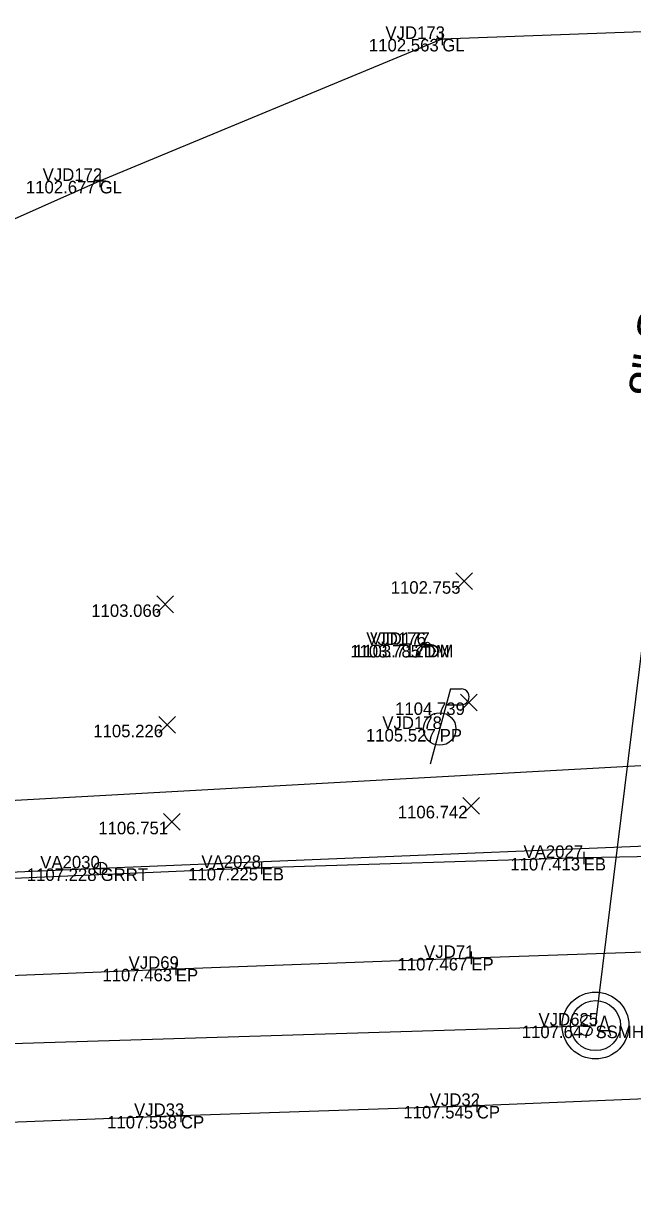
# Model space of a CAD drawing. Extents: x 1629915 to 1630675, y 484401 to 484601.
# Drawn here: x 1630207 to 1630255.7, y 484481.8 to 484574.6 of the extents above; entities that cross this region are included whole.
import ezdxf

# ---------------------------------------------------------------- set-up
doc = ezdxf.new("R2010")
doc.units = 0
for name, color, linetype in [('Default', 7, 'Continuous'), ('DR_X_Storm_Sewer', 7, 'Continuous'), ('GK_Drainage_Nodes', 7, 'Continuous'), ('PV_X_COP', 7, 'Continuous'), ('PV_X_EOP', 7, 'Continuous'), ('PV_X_Shoulder_Aggregate', 7, 'Continuous'), ('RD_X_GR_Rt', 7, 'Continuous'), ('SC_Scratch2', 7, 'Continuous'), ('SV_X_Random_Point', 7, 'Continuous'), ('SV_X_Shot_Marker', 7, 'Continuous'), ('SV_X_Text_Comment', 7, 'Continuous'), ('SV_X_Text_Elevation', 7, 'Continuous'), ('SV_X_Text_Name', 7, 'Continuous'), ('TX_X_20', 7, 'Continuous'), ('UT_X_Electric_Cells', 7, 'Continuous'), ('UT_X_Gas', 7, 'Continuous'), ('UT_X_Misc_Cells', 7, 'Continuous'), ('UT_X_Sanitary_Cells', 7, 'Continuous'), ('UT_X_Sanitary_Line', 7, 'Continuous')]:
    doc.layers.add(name, color=color, linetype=linetype)

# ---------------------------------------------------------------- blocks, each defined once
blk = doc.blocks.new('SurveyPointCell')
at = {"layer": 'Default'}
for p, q in [((-0.5, 0), (0.5, 0)), ((0, -0.5), (0, 0.5))]:
    blk.add_line(p, q, dxfattribs=at)
blk.add_circle((0, 0), 0.5, dxfattribs=at)

msp = doc.modelspace()

# ---------------------------------------------------------------- linework, layer by layer
at = {"layer": 'DR_X_Storm_Sewer'}
msp.add_line((1630034.139, 484503.088), (1630277.798, 484516.548), dxfattribs=at)
at = {"layer": 'GK_Drainage_Nodes'}
for p, q in [((1630252.717, 484496.605), (1630252.717, 484496.605)), ((1630252.717, 484494.605), (1630252.717, 484494.605)), ((1630252.717, 484494.605), (1630252.717, 484494.605)), ((1630252.717, 484494.605), (1630252.717, 484494.605)), ((1630252.717, 484492.605), (1630252.717, 484492.605))]:
    msp.add_line(p, q, dxfattribs=at)
msp.add_circle((1630252.717, 484494.605), 2, dxfattribs=at)
at = {"layer": 'PV_X_COP'}
msp.add_lwpolyline([(1630268.327, 484489.246), (1630243.236, 484488.193), (1630219.614, 484487.396), (1630181.886, 484485.929), (1630141.907, 484484.591), (1630101.847, 484483.155), (1630058.972, 484481.674), (1630018.452, 484480.335), (1629978.036, 484478.791), (1629939.203, 484477.211)], dxfattribs=at)
at = {"layer": 'PV_X_EOP'}
msp.add_lwpolyline([(1629938.787, 484488.624), (1629977.755, 484490.201), (1630018.109, 484491.66), (1630058.596, 484492.972), (1630101.458, 484494.639), (1630141.527, 484496.094), (1630181.4, 484497.615), (1630219.199, 484499.135), (1630242.799, 484500.003), (1630272.749, 484501.051)], dxfattribs=at)
at = {"layer": 'PV_X_Shoulder_Aggregate'}
msp.add_lwpolyline([(1630275.858, 484507.82), (1630275.935, 484508.43), (1630251.773, 484507.981), (1630226.056, 484507.184), (1630204.993, 484506.289), (1630180.178, 484504.732), (1630155.752, 484502.786), (1630130.505, 484501.377), (1630107.341, 484499.869), (1630082.614, 484498.877), (1630057.423, 484497.854), (1630056.684, 484498.178), (1630055.974, 484498.791), (1630036.737, 484497.117), (1630036.516, 484496.78), (1630005.439, 484492.996), (1629981.146, 484491.329), (1629968.094, 484490.842), (1629967.166, 484490.748), (1629965.306, 484491.801), (1629947.85, 484491.524), (1629935.773, 484490.2), (1629921.037, 484489.433)], dxfattribs=at)
at = {"layer": 'RD_X_GR_Rt'}
msp.add_lwpolyline([(1630276.942, 484509.755), (1630213.199, 484507.144), (1630188.359, 484506.044), (1630165.142, 484504.69)], dxfattribs=at)
at = {"layer": 'SV_X_Random_Point'}
for p, q in [((1630241.562, 484529.396), (1630242.896, 484530.731)), ((1630241.562, 484530.731), (1630242.896, 484529.396)), ((1630217.683, 484527.547), (1630219.017, 484528.882)), ((1630217.683, 484528.882), (1630219.017, 484527.547)), ((1630241.925, 484519.721), (1630243.258, 484521.056)), ((1630241.925, 484521.056), (1630243.258, 484519.721)), ((1630217.844, 484517.943), (1630219.178, 484519.278)), ((1630217.844, 484519.278), (1630219.178, 484517.943)), ((1630242.129, 484511.472), (1630243.462, 484512.807)), ((1630242.129, 484512.807), (1630243.462, 484511.472)), ((1630218.225, 484510.198), (1630219.559, 484511.533)), ((1630218.225, 484511.533), (1630219.559, 484510.198))]:
    msp.add_line(p, q, dxfattribs=at)
at = {"layer": 'SV_X_Shot_Marker'}
for p, q in [((1630239.982, 484573.334), (1630240.982, 484573.334)), ((1630240.482, 484573.834), (1630240.482, 484572.834)), ((1630240.482, 484573.334), (1630240.482, 484573.334)), ((1630213.122, 484562.506), (1630213.122, 484561.506)), ((1630212.622, 484562.006), (1630213.622, 484562.006)), ((1630213.122, 484562.006), (1630213.122, 484562.006)), ((1630251.773, 484508.481), (1630251.773, 484507.481)), ((1630226.056, 484507.684), (1630226.056, 484506.684)), ((1630251.273, 484507.981), (1630252.273, 484507.981)), ((1630251.773, 484507.981), (1630251.773, 484507.981)), ((1630225.556, 484507.184), (1630226.556, 484507.184)), ((1630226.056, 484507.184), (1630226.056, 484507.184)), ((1630242.299, 484500.003), (1630243.299, 484500.003)), ((1630242.799, 484500.503), (1630242.799, 484499.503)), ((1630242.799, 484500.003), (1630242.799, 484500.003)), ((1630218.699, 484499.135), (1630219.699, 484499.135)), ((1630219.199, 484499.635), (1630219.199, 484498.635)), ((1630219.199, 484499.135), (1630219.199, 484499.135)), ((1630219.614, 484487.896), (1630219.614, 484486.896)), ((1630242.736, 484488.193), (1630243.736, 484488.193)), ((1630243.236, 484488.693), (1630243.236, 484487.693)), ((1630243.236, 484488.193), (1630243.236, 484488.193)), ((1630219.114, 484487.396), (1630220.114, 484487.396)), ((1630219.614, 484487.396), (1630219.614, 484487.396))]:
    msp.add_line(p, q, dxfattribs=at)
at = {"layer": 'UT_X_Electric_Cells'}
for p, q in [((1630241.131, 484521.47), (1630239.525, 484515.47)), ((1630241.131, 484521.47), (1630241.981, 484521.47)), ((1630240.79, 484520.195), (1630241.981, 484520.195))]:
    msp.add_line(p, q, dxfattribs=at)
msp.add_circle((1630240.275, 484518.27), 1.3, dxfattribs=at)
msp.add_arc((1630241.994, 484520.832), 0.638, 268.8767, 91.1233, dxfattribs=at)
at = {"layer": 'UT_X_Gas'}
for points in [[(1630098.571, 484496.166), (1630109.658, 484497.037), (1630113.017, 484497.698), (1630113.953, 484498.758), (1630114.05, 484508.257), (1630114.557, 484509.569), (1630115.808, 484510.855), (1630129.42, 484519.99), (1630159.397, 484536.236), (1630181.581, 484547.984), (1630213.122, 484562.006), (1630240.482, 484573.334), (1630274.591, 484574.583), (1630290.006, 484572.984), (1630327.07, 484564.379), (1630366.658, 484567.361), (1630393.117, 484565.898), (1630419.955, 484549.235), (1630440.635, 484526.36), (1630450.487, 484510.253), (1630452.083, 484508.491), (1630453.278, 484508.551), (1630468.94, 484509.134)], [(1630098.571, 484496.166), (1630109.658, 484497.037), (1630113.017, 484497.698), (1630113.953, 484498.758), (1630114.05, 484508.257), (1630114.557, 484509.569), (1630115.808, 484510.855), (1630129.42, 484519.99), (1630159.397, 484536.236), (1630181.581, 484547.984), (1630213.122, 484562.006), (1630240.482, 484573.334), (1630274.591, 484574.583), (1630290.006, 484572.984), (1630327.07, 484564.379), (1630366.658, 484567.361), (1630393.117, 484565.898), (1630419.955, 484549.235), (1630440.635, 484526.36), (1630450.487, 484510.253), (1630452.083, 484508.491), (1630453.278, 484508.551), (1630494.384, 484510.081)]]:
    msp.add_lwpolyline(points, dxfattribs=at)
at = {"layer": 'UT_X_Misc_Cells'}
for centre in [(1630238.999, 484524.976), (1630239.297, 484524.988)]:
    msp.add_circle(centre, 0.2, dxfattribs=at)
for centre, start, end in [((1630239.204, 484524.203), 14.81337, 194.81337), ((1630239.461, 484524.205), 11.84523, 191.84523)]:
    msp.add_arc(centre, 0.8, start, end, dxfattribs=at)
at = {"layer": 'UT_X_Sanitary_Cells'}
for points in [[(1630252.385, 484495.291), (1630252.36, 484495.316), (1630252.322, 484495.341), (1630252.208, 484495.379), (1630252.07, 484495.405), (1630251.969, 484495.405), (1630251.931, 484495.405), (1630251.767, 484495.367), (1630251.629, 484495.291), (1630251.541, 484495.19), (1630251.516, 484495.089), (1630251.516, 484495.014), (1630251.541, 484494.913), (1630251.641, 484494.825), (1630252.334, 484494.447), (1630252.397, 484494.397), (1630252.423, 484494.346), (1630252.448, 484494.271), (1630252.448, 484494.195), (1630252.435, 484494.12), (1630252.423, 484494.069), (1630252.397, 484494.006), (1630252.372, 484493.956), (1630252.347, 484493.918), (1630252.309, 484493.88), (1630252.271, 484493.855), (1630252.221, 484493.83), (1630252.183, 484493.817), (1630252.07, 484493.805), (1630251.893, 484493.805), (1630251.78, 484493.83), (1630251.616, 484493.918), (1630251.516, 484493.994)], [(1630252.926, 484493.805), (1630253.43, 484495.405), (1630253.922, 484493.805)], [(1630253.796, 484494.182), (1630253.052, 484494.182)]]:
    msp.add_lwpolyline(points, dxfattribs=at)
for radius in [2.667, 2]:
    msp.add_circle((1630252.717, 484494.605), radius, dxfattribs=at)
at = {"layer": 'UT_X_Sanitary_Line'}
msp.add_lwpolyline([(1629930.746, 484483.734), (1630048.132, 484488.308), (1630252.717, 484494.605), (1630261.76, 484567.793), (1630373.422, 484500.095), (1630654.857, 484509.349)], dxfattribs=at)

# ---------------------------------------------------------------- block references
at = {"layer": 'SC_Scratch2'}
msp.add_blockref('SurveyPointCell', (1630213.199, 484507.144), dxfattribs=at)

# ---------------------------------------------------------------- texts
at = {"layer": 'SV_X_Text_Comment'}
for s, p in [('GL', (1630240.482, 484572.334)), ('GL', (1630213.122, 484561.006)), ('DM', (1630238.999, 484523.976)), ('DM', (1630239.297, 484523.988)), ('PP', (1630240.275, 484517.27)), ('EB', (1630251.773, 484506.981)), ('GRRT', (1630213.199, 484506.144)), ('EB', (1630226.056, 484506.184)), ('EP', (1630242.799, 484499.003)), ('EP', (1630219.199, 484498.135)), ('SSMH', (1630252.717, 484493.605)), ('CP', (1630243.236, 484487.193)), ('CP', (1630219.614, 484486.396))]:
    msp.add_text(s, height=1, dxfattribs=at).set_placement(p)
at = {"layer": 'SV_X_Text_Elevation'}
for s, p in [('1102.563', (1630234.62, 484572.334)), ('1102.677', (1630207.228, 484561.006)), ('1102.755', (1630236.361, 484529.063)), ('1103.066', (1630212.448, 484527.215)), ('1103.785', (1630233.131, 484523.976)), ('1103.712', (1630233.425, 484523.988)), ('1104.739', (1630236.71, 484519.388)), ('1105.226', (1630212.609, 484517.611)), ('1105.527', (1630234.381, 484517.27)), ('1106.742', (1630236.924, 484511.139)), ('1106.751', (1630213.012, 484509.865)), ('1107.413', (1630245.911, 484506.981)), ('1107.228', (1630207.3, 484506.144)), ('1107.225', (1630220.187, 484506.184)), ('1107.467', (1630236.905, 484499.003)), ('1107.463', (1630213.337, 484498.135)), ('1107.647', (1630246.824, 484493.605)), ('1107.545', (1630237.368, 484487.193)), ('1107.558', (1630213.716, 484486.396))]:
    msp.add_text(s, height=1, dxfattribs=at).set_placement(p)
at = {"layer": 'SV_X_Text_Name'}
for s, p in [('VJD173', (1630235.938, 484573.334)), ('VJD172', (1630208.569, 484562.006)), ('VJD176', (1630234.415, 484524.976)), ('VJD177', (1630234.721, 484524.988)), ('VJD178', (1630235.694, 484518.27)), ('VA2027', (1630246.966, 484507.981)), ('VA2030', (1630208.375, 484507.144)), ('VA2028', (1630221.245, 484507.184)), ('VJD71', (1630239.036, 484500.003)), ('VJD69', (1630215.434, 484499.135)), ('VJD625', (1630248.167, 484494.605)), ('VJD32', (1630239.481, 484488.193)), ('VJD33', (1630215.869, 484487.396))]:
    msp.add_text(s, height=1, dxfattribs=at).set_placement(p)
at = {"layer": 'TX_X_20'}
msp.add_text('8" SAN', height=2.8, rotation=82.28682, dxfattribs=at).set_placement((1630258.104, 484544.58))

doc.saveas('drawing.dxf')
